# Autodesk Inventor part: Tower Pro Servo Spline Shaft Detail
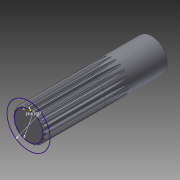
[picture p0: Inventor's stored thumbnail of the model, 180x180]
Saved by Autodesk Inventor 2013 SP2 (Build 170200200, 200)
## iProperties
Created: 2020-02
Part Number: Tower Pro Servo Spline Shaft Detail
Material: Steel
Document SubType Name: Modeling
Designer: DELL
Density: 1 g/cm^3
CustomPartVersion: 1
Author: DELL
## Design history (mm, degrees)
sketch "Sketch3"
  geometry: C1 r 2.6 at (0, 0); 1 further point
  constraints: 1 centre point, 1 coincident
  dimensions: "d16" = 5.2 diameter of C1
extrude "Extrusion1" new body sketch "Sketch3" distance "d18" = 20; taper "d19" = 0 deg
chamfer "Chamfer4" distance "d21" = 0.25; stored, may be unused: second distance "d22" = 2, angle "d23" = 45 deg
sketch "Sketch4"
  geometry: L1 (0, 0)-(1.12, 2.704); L2 (0, -3.751)-(0, 3.779) reference; L3 (0, 0)-(-1.12, 2.704); L4 (0.643, 1.552)-(-1.571, 2.469); C1 r 2.375 at (0, 0); C2 r 2.475 at (0, 0); C3 r 2.183 at (0, 0); C4 r 1.68 at (0, 0); 1 further point
  constraints: 6 end point, 4 centre point, 4 coincident, 1 perpendicular, 1 point on line, 1 tangent
  dimensions: "d46" = 4.75 diameter of C1; "d48" = 4.95 diameter of C2; "d49" = 4.367 diameter of C3; "d50" = 3.359 diameter of C4; "d52" = 22.5 deg angle of L1 L2; "d53" = 45 deg angle of L1 L3
sketch "Sketch5"
  geometry: L1 (0, -1.686)-(-0.333, -2.668); L2 (0, -1.686)-(0.336, -2.675); L3 (0, -3.751)-(0, 3.779) reference; 5 further points
  constraints: 4 end point, 2 other
  dimensions: "d54" = 1.6862 distance of L1.start point (0, 0); "d55" = 18.75 deg angle of L2 L3; "d56" = 18.75 deg angle of L3 L1 (= d55); "d57" = 37.5 deg angle of L2 L1 (derived)
node "Involute Splining9"
sketch "Sketch6" dims "d64" = 4.61623 (derived)
  geometry: C1 r 3.5 at (0, 0); A1 r 2.308 centre (0, 0) between (0.414, 2.271) and (0.308, 2.287) reference; A2 r 1.037 centre (-0.708, 1.95) between (0.259, 2.327) and (0.255, 2.336) reference; A3 r 0.063 centre (0.317, 2.349) between (0.259, 2.327) and (0.308, 2.287) reference; 3 further points
  constraints: 2 coincident, 1 centre point, 4 other
  dimensions: "d61" = 7 diameter of C1
body "Solid2"
feature "Shaft Groove"
